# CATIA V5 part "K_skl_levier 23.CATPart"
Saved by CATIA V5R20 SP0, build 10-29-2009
Part number: skl_levier 23
Publications: "longueur axe pivot", "liaison 10/23 sur 23", "liaison 57/23", "Plan.-30", "Droite.1", "Droite.2", "Droite.3"
Bounding box of the stored display mesh (mm): x -30 to 120, y -990 to -720, z 360 to 725
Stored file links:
  G:\Khaled_CFAO_2011\SIL\SIL_GR2\mdardier\Khaled\CAD_ThinkMOTION\K_skl_levier 23.CATPart
  G:\Khaled_CFAO_2011\SIL\SIL_GR2\mdardier\Khaled\CAD_ThinkMOTION\K_skl_ass_tandem.CATProduct
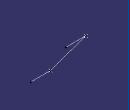
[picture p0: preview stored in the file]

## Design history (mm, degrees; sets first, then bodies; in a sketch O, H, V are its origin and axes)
External parameters (linked from other documents)
  `External.longueur axe pivot` = 150 mm
Set1
  Point1 "liaison 10/23 sur 23": linked copy from another document
  Point2 "liaison 57/23": linked copy from another document
  Plane1 "Plan.-30": linked copy from another document
Set2
  Line1: type PtPt, FirstPoint Point1, SecondPoint Point2
  Line2: type Normal, RefPoint Point1, RefSkin Plane1, Start 0, End 150 {= `External.longueur axe pivot`}
  Line3: type Normal, RefPoint Point2, RefSkin Plane1, Start 0, End 150 {= `External.longueur axe pivot`}
Body1 (main body)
